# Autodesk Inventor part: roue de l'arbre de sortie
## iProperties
Shininess: 64.0
Length Units: 11269
Angle Units: 11279
Time Units: 11290
Mass Units: 11283
Length Display Precision: 3
Angle Display Precision: 2
Compacted: True
Part Number: roue de l'arbre de sortie
Document SubType Name: Modeling
Created: 2004-09
Material: Par défaut
Designer: Laurent
Density: 1 g/cm^3
Density: 0.0
Volumn: 0.0
Area: 0.0
PropertySet Name: Model Information
Control State: 0
Master: False
Checked Out: False
Author: Laurent
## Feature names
1. Extrusion1
2. Extrusion2
3. Extrusion3
4. Extrusion10
5. Réseau circulaire1 [Circular Pattern]
